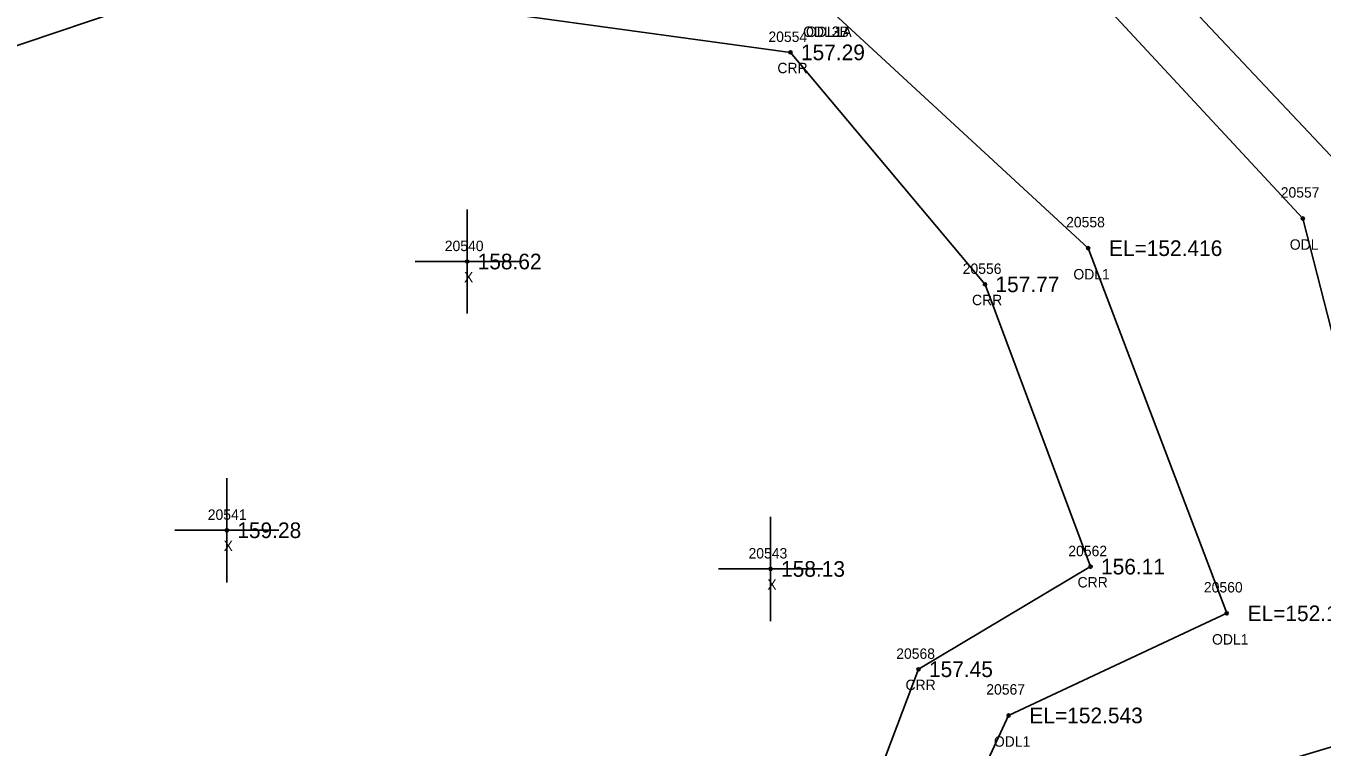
# Model space of a CAD drawing. Extents: x 2279528 to 2280976, y 1061373 to 1062235.
# Drawn here: x 2280192.7 to 2280317.1, y 1061681.1 to 1061750.3 of the extents above; entities that cross this region are included whole.
import ezdxf

# ---------------------------------------------------------------- set-up
doc = ezdxf.new("R2010")
doc.units = 0
for name, color, linetype in [('RD_DTM_BkLn2', 7, 'Continuous'), ('RD_EX_H2O', 7, 'Continuous'), ('RD_EX_H2O_txCode', 7, 'Continuous'), ('RD_EX_Misc', 7, 'Continuous'), ('RD_EX_Misc_txCode', 7, 'Continuous'), ('RD_EX_TX_H2O_ELEV', 7, 'Continuous'), ('RD_EX_TX_Misc_ELEV', 7, 'Continuous'), ('RD_SMD_Locator', 7, 'Continuous')]:
    doc.layers.add(name, color=color, linetype=linetype)

msp = doc.modelspace()

# ---------------------------------------------------------------- linework, layer by layer
at = {"layer": 'RD_DTM_BkLn2'}
msp.add_lwpolyline([(2280066.92, 1061680.28), (2280073.37, 1061687.57), (2280161.47, 1061729), (2280173.75, 1061738.9), (2280180.46, 1061744.56), (2280207.84, 1061753.79), (2280214.1, 1061757.73), (2280223.01, 1061764.94)], dxfattribs=at)
at = {"layer": 'RD_EX_H2O'}
for points in [[(2280243.56, 1061789.13), (2280258.67, 1061797.27), (2280267.66, 1061787.82), (2280287.8, 1061761.36), (2280315.22, 1061731.8), (2280327.48, 1061683.93), (2280307.76, 1061678.04), (2280294.04, 1061661.65), (2280295.74, 1061631.81), (2280310.81, 1061587.94), (2280304.48, 1061546.39), (2280272.84, 1061527.93), (2280259.98, 1061540.36), (2280245.21, 1061537.05), (2280265.99, 1061500.75), (2280299.66, 1061476.28), (2280353.73, 1061471.3), (2280375.17, 1061457.42), (2280376.85, 1061433.19), (2280358.1, 1061419.49), (2280333.32, 1061393.34)], [(2280269.9, 1061794.49), (2280270.02, 1061790.74), (2280293.77, 1061763.48), (2280320.49, 1061735.05), (2280335.4, 1061680.01), (2280309.48, 1061674.63), (2280300.03, 1061660.41), (2280304.47, 1061633.12), (2280315.65, 1061587.64), (2280305.89, 1061543.57), (2280270.77, 1061524.54), (2280257.61, 1061536.28), (2280249.22, 1061535.26), (2280269.33, 1061502.83), (2280301.34, 1061480.02), (2280355.94, 1061475.37), (2280377.91, 1061459.94), (2280379.03, 1061433), (2280360.13, 1061417.18), (2280333.79, 1061387.95)], [(2280219.49, 1061771.9), (2280219.45, 1061768.68), (2280220.02, 1061767.07), (2280223.01, 1061764.94), (2280232.42, 1061752.34), (2280266.07, 1061747.74), (2280284.73, 1061725.48), (2280294.86, 1061698.39), (2280278.35, 1061688.54), (2280267.33, 1061659.35), (2280270.69, 1061629.09), (2280284.25, 1061605.42), (2280287.8, 1061578.54), (2280274.54, 1061562.25), (2280261.24, 1061561.71), (2280231.85, 1061561.45), (2280221.24, 1061537.21), (2280230.8, 1061514.2), (2280261.74, 1061476.46), (2280301.47, 1061455.38), (2280325.75, 1061454.26), (2280345.44, 1061445.29), (2280345.67, 1061436.49), (2280313.46, 1061411.55)], [(2280269.44, 1061752.22), (2280294.62, 1061728.95), (2280307.92, 1061693.91), (2280286.99, 1061684.11), (2280274.68, 1061657.45), (2280275.58, 1061630.25), (2280288.86, 1061608.44), (2280293.72, 1061581.7), (2280282.36, 1061552.42), (2280261.54, 1061554.57), (2280239.33, 1061554.65), (2280227, 1061538.36), (2280233.84, 1061514.57), (2280265.76, 1061478.91), (2280302.98, 1061460.15), (2280326.03, 1061460.1), (2280352.94, 1061451.17), (2280354.09, 1061431.94), (2280317.15, 1061398.72)]]:
    msp.add_lwpolyline(points, dxfattribs=at)
at = {"layer": 'RD_EX_Misc'}
for p, q in [((2280235.05, 1061722.67), (2280235.05, 1061732.67)), ((2280230.05, 1061727.67), (2280240.05, 1061727.67)), ((2280211.99, 1061696.88), (2280211.99, 1061706.88)), ((2280264.16, 1061693.17), (2280264.16, 1061703.17)), ((2280206.99, 1061701.88), (2280216.99, 1061701.88)), ((2280259.16, 1061698.17), (2280269.16, 1061698.17))]:
    msp.add_line(p, q, dxfattribs=at)
at = {"layer": 'RD_SMD_Locator'}
for centre in [(2280266.07, 1061747.74), (2280315.22, 1061731.8), (2280294.62, 1061728.95), (2280235.05, 1061727.67), (2280284.73, 1061725.48), (2280211.99, 1061701.88), (2280264.16, 1061698.17), (2280294.86, 1061698.39), (2280307.92, 1061693.91), (2280278.35, 1061688.54), (2280286.99, 1061684.11)]:
    msp.add_circle(centre, 0.15, dxfattribs=at)

# ---------------------------------------------------------------- texts
at = {"layer": 'RD_EX_H2O_txCode'}
for s, p in [('ODL2B', (2280267.28, 1061749.22)), ('ODL3B', (2280267.28, 1061749.22)), ('ODL1A', (2280267.55, 1061749.22)), ('20554', (2280263.95, 1061748.74)), ('CRR', (2280264.81, 1061745.74)), ('20557', (2280313.1, 1061733.8)), ('20558', (2280292.51, 1061730.95)), ('ODL', (2280313.97, 1061728.8)), ('20556', (2280282.59, 1061726.48)), ('ODL1', (2280293.21, 1061725.95)), ('CRR', (2280283.48, 1061723.48)), ('20562', (2280292.72, 1061699.39)), ('CRR', (2280293.61, 1061696.39)), ('20560', (2280305.73, 1061695.91)), ('ODL1', (2280306.51, 1061690.91)), ('20568', (2280276.21, 1061689.54)), ('CRR', (2280277.1, 1061686.54)), ('20567', (2280284.85, 1061686.11)), ('ODL1', (2280285.58, 1061681.11))]:
    msp.add_text(s, height=1, dxfattribs=at).set_placement(p)
at = {"layer": 'RD_EX_Misc_txCode'}
for s, p in [('20540', (2280232.9, 1061728.67)), ('X', (2280234.74, 1061725.67)), ('20541', (2280210.16, 1061702.88)), ('X', (2280211.68, 1061699.88)), ('20543', (2280262.04, 1061699.17)), ('X', (2280263.84, 1061696.17))]:
    msp.add_text(s, height=1, dxfattribs=at).set_placement(p)
at = {"layer": 'RD_EX_TX_H2O_ELEV'}
for s, p in [('157.29', (2280267.07, 1061746.99)), ('EL=152.416', (2280296.62, 1061728.2)), ('157.77', (2280285.73, 1061724.73)), ('156.11', (2280295.86, 1061697.64)), ('EL=152.157', (2280309.92, 1061693.16)), ('157.45', (2280279.35, 1061687.79)), ('EL=152.543', (2280288.99, 1061683.36))]:
    msp.add_text(s, height=1.5, dxfattribs=at).set_placement(p)
at = {"layer": 'RD_EX_TX_Misc_ELEV'}
for s, p in [('158.62', (2280236.05, 1061726.92)), ('159.28', (2280212.99, 1061701.13)), ('158.13', (2280265.16, 1061697.42))]:
    msp.add_text(s, height=1.5, dxfattribs=at).set_placement(p)

doc.saveas('drawing.dxf')
